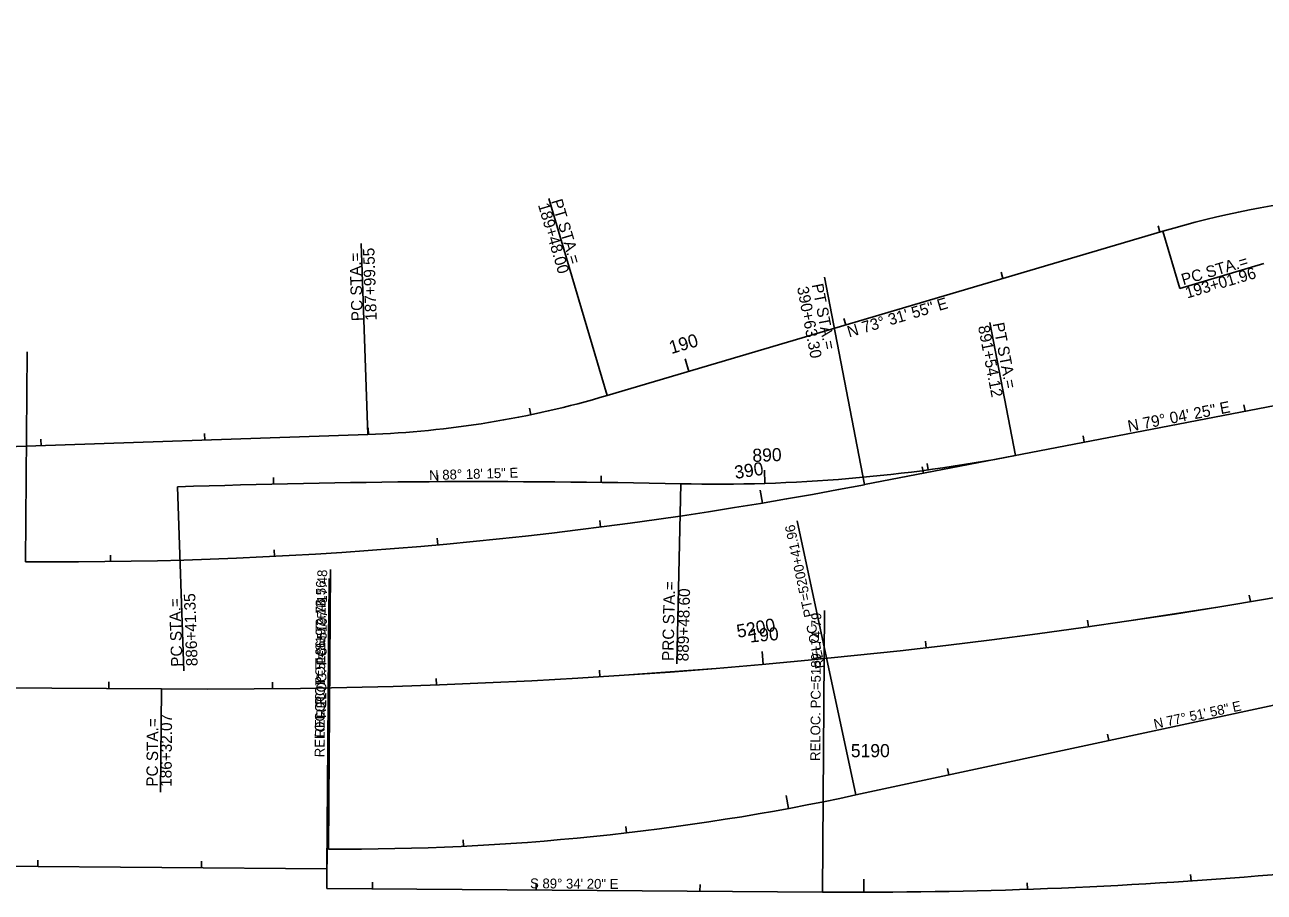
# Model space of a CAD drawing. Extents: x 1944333 to 1978554, y 788952 to 827675.
# Drawn here: x 1969909 to 1970666, y 802183 to 802712 of the extents above; entities that cross this region are included whole.
import ezdxf

# ---------------------------------------------------------------- set-up
doc = ezdxf.new("R2010")
doc.units = 0
for name, color, linetype in [('RD_HC_CL_Rel', 7, 'Continuous'), ('RD_HC_Data_Rel', 7, 'Continuous'), ('RD_HC_Data_Tic_Rel', 7, 'Continuous'), ('RD_HC_TX_Rel_Sta50', 7, 'Continuous')]:
    doc.layers.add(name, color=color, linetype=linetype)

msp = doc.modelspace()

# ---------------------------------------------------------------- linework, layer by layer
at = {"layer": 'RD_HC_CL_Rel'}
for p, q in [((1970264.5, 802485.88), (1970603.94, 802586.22)), ((1970421.68, 802431.47), (1970731.55, 802491.29)), ((1968886.72, 802419.62), (1970118.36, 802462.15)), ((1970416.45, 802242.04), (1970836.61, 802332.37)), ((1969096.67, 802313.47), (1969992.37, 802306.78)), ((1969096.67, 802313.47), (1969992.37, 802306.78)), ((1969095.86, 802204.47), (1970093.44, 802197.02)), ((1970093.35, 802185.02), (1970396, 802182.76))]:
    msp.add_line(p, q, dxfattribs=at)
for centre, radius, start, end in [((1970020.89, 806126.39), 3819.72, 269.57213, 296.64085), ((1970020.89, 806126.4), 3819.72, 269.57213, 296.64085), ((1970770.34, 802023.3), 587, 85.2802, 106.46812), ((1970098.1, 803048.8), 587, 271.97804, 286.46812), ((1970330.96, 803396.77), 965, 268.72404, 280.9265), ((1969928.85, 804984.33), 2600, 269.57213, 280.9265), ((1970189, 797023.35), 5410, 88.72404, 91.97804), ((1970105.36, 803688.98), 1480, 269.57213, 282.13386), ((1970418.4, 805182.68), 3000, 269.57213, 280.07183)]:
    msp.add_arc(centre, radius, start, end, dxfattribs=at)
at = {"layer": 'RD_HC_Data_Rel'}
for p, q in [((1970264.5, 802485.88), (1970228.94, 802606.21)), ((1970603.94, 802586.22), (1970614.27, 802551.29)), ((1970118.36, 802462.15), (1970114.34, 802578.64)), ((1970614.27, 802551.29), (1970665.52, 802566.44)), ((1970421.68, 802431.47), (1970397.23, 802558.09)), ((1970513.88, 802449.27), (1970498.2, 802530.45)), ((1969909.43, 802384.4), (1969910.39, 802512.65)), ((1970002.27, 802430.13), (1970006.15, 802317.81)), ((1970309.47, 802432.01), (1970307.02, 802322.06)), ((1970416.45, 802242.04), (1970380.49, 802409.33)), ((1970093.44, 802197.02), (1970094.76, 802374.25)), ((1970094.31, 802209.02), (1970095.58, 802379.76)), ((1970093.35, 802185.02), (1970094.66, 802361.01)), ((1970396, 802182.76), (1970397.28, 802354.56)), ((1969992.37, 802306.78), (1969991.9, 802243.73))]:
    msp.add_line(p, q, dxfattribs=at)
at = {"layer": 'RD_HC_Data_Tic_Rel'}
for p, q in [((1970602.06, 802585.67), (1970600.93, 802589.51)), ((1970506.16, 802557.32), (1970505.03, 802561.16)), ((1970410.27, 802528.97), (1970409.13, 802532.81)), ((1970314.37, 802500.62), (1970312.1, 802508.3)), ((1970654.09, 802476.33), (1970653.33, 802480.26)), ((1970217.97, 802474.17), (1970217.15, 802478.09)), ((1970118.81, 802462.17), (1970118.67, 802466.17)), ((1969918.93, 802455.27), (1969918.79, 802459.26)), ((1970018.87, 802458.72), (1970018.73, 802462.72)), ((1970555.9, 802457.38), (1970555.15, 802461.31)), ((1970457.72, 802438.42), (1970456.96, 802442.35)), ((1970460.48, 802440.5), (1970459.94, 802444.47)), ((1970060.89, 802431.83), (1970060.8, 802435.83)), ((1970160.88, 802433.28), (1970160.86, 802437.28)), ((1970260.88, 802432.87), (1970260.93, 802436.87)), ((1970360.87, 802432.23), (1970360.62, 802440.23)), ((1970359.39, 802420.23), (1970358.07, 802428.12)), ((1970260.48, 802405.57), (1970259.97, 802409.53)), ((1970161.07, 802394.72), (1970160.72, 802398.71)), ((1969961.38, 802384.53), (1969961.33, 802388.53)), ((1970061.33, 802387.71), (1970061.12, 802391.7)), ((1970657.31, 802360.07), (1970656.65, 802364.01)), ((1970657.31, 802360.07), (1970656.65, 802364.01)), ((1970558.5, 802344.7), (1970557.94, 802348.66)), ((1970558.5, 802344.7), (1970557.94, 802348.66)), ((1970459.33, 802331.92), (1970458.87, 802335.89)), ((1970459.33, 802331.92), (1970458.87, 802335.89)), ((1970359.85, 802321.74), (1970359.14, 802329.71)), ((1970359.85, 802321.74), (1970359.14, 802329.71)), ((1970160.26, 802309.22), (1970160.12, 802313.22)), ((1970160.26, 802309.22), (1970160.12, 802313.22)), ((1970260.14, 802314.18), (1970259.89, 802318.17)), ((1970260.14, 802314.18), (1970259.89, 802318.17)), ((1969960.3, 802307.02), (1969960.33, 802311.02)), ((1969960.3, 802307.02), (1969960.33, 802311.02)), ((1970060.29, 802306.88), (1970060.25, 802310.88)), ((1970060.29, 802306.88), (1970060.25, 802310.88)), ((1970570.96, 802275.26), (1970570.12, 802279.17)), ((1970473.2, 802254.24), (1970472.36, 802258.15)), ((1970375.31, 802233.8), (1970373.85, 802241.67)), ((1970276.45, 802218.9), (1970275.98, 802222.87)), ((1970176.8, 802210.7), (1970176.61, 802214.7)), ((1969916.88, 802198.34), (1969916.91, 802202.34)), ((1970016.88, 802197.6), (1970016.91, 802201.6)), ((1970621.05, 802189.53), (1970620.78, 802193.52)), ((1970121.22, 802184.82), (1970121.25, 802188.82)), ((1970221.21, 802184.07), (1970221.24, 802188.07)), ((1970321.21, 802183.32), (1970321.24, 802187.32)), ((1970421.21, 802182.68), (1970421.2, 802190.68)), ((1970521.19, 802184.44), (1970521.05, 802188.44))]:
    msp.add_line(p, q, dxfattribs=at)

# ---------------------------------------------------------------- texts
at = {"layer": 'RD_HC_Data_Rel'}
for s, height, rotation, p in [('189+48.00', 7, 286.46812, (1970222.22, 802602.28)), ('PT STA.=', 7, 286.46812, (1970230.28, 802604.66)), ('PC STA.=', 7, 91.97804, (1970115.49, 802531.41)), ('187+99.55', 7, 91.97804, (1970123.89, 802531.7)), ('PC STA.=', 7, 16.46812, (1970616.33, 802553.14)), ('193+01.96', 7, 16.46812, (1970618.71, 802545.08)), ('390+63.30', 7, 280.9265, (1970380.45, 802551.8)), ('PT STA.=', 7, 280.9265, (1970389.46, 802553.54)), ('N 73%%d 31\' 55" E', 7, 16.46812, (1970412.28, 802521.26)), ('891+54.12', 7, 280.9265, (1970490.96, 802528.03)), ('PT STA.=', 7, 280.9265, (1970499.97, 802529.77)), ('N 79%%d 04\' 25" E', 7, 10.9265, (1970583.1, 802463.65)), ('N 88%%d 18\' 15" E', 6, 1.69582, (1970155.94, 802434.24)), ('RELOC. PT=5200+41.96', 6, 102.13386, (1970397.68, 802319.83)), ('RELOC. PC=5197+17.48', 6, 89.57213, (1970092.91, 802289.03)), ('RELOC. POT=8197+76.56', 6, 89.57213, (1970092.03, 802277.04)), ('PRC STA.=', 7, 88.72404, (1970305.04, 802323.76)), ('889+48.60', 7, 88.72404, (1970314.21, 802323.56)), ('PC STA.=', 7, 91.97804, (1970005.36, 802320.43)), ('886+41.35', 7, 91.97804, (1970014.53, 802320.75)), ('RELOC. POT=5186+72.13', 6, 89.57213, (1970091.94, 802265.04)), ('RELOC. PC=5189+74.79', 6, 89.57213, (1970394.59, 802262.78)), ('N 77%%d 51\' 58" E', 6, 12.13386, (1970598.97, 802282.3)), ('186+32.07', 7, 89.57213, (1969998.57, 802246.98)), ('PC STA.=', 7, 89.57213, (1969990.17, 802247.05)), ('S 89%%d 34\' 20" E', 6, 359.57213, (1970217.44, 802185.1))]:
    msp.add_text(s, height=height, rotation=rotation, dxfattribs=at).set_placement(p)
at = {"layer": 'RD_HC_TX_Rel_Sta50'}
for s, rotation, p in [('190', 16.46812, (1970303.72, 802511.14)), ('890', 1.77586, (1970353.34, 802445.33)), ('390', 8.52764, (1970342.83, 802434.92)), ('5200', 10.50947, (1970344.39, 802337.91)), ('190', 5.09103, (1970351.81, 802335.09)), ('5190', 0.05365, (1970413.33, 802265.09))]:
    msp.add_text(s, height=8, rotation=rotation, dxfattribs=at).set_placement(p)

doc.saveas('drawing.dxf')
